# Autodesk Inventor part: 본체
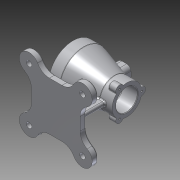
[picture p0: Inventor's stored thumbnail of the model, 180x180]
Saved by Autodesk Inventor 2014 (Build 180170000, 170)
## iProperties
Created: 2018-03
Part Number: 본체
Material: 알루미늄 6061
Document SubType Name: Modeling
Designer: kb542
Density: 2.71 g/cm^3
Appearance: 알루미늄 - 평지
Author: kb542
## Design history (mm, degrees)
sketch "스케치1"
  geometry: L1 (-50, 0)-(50, 0); L2 (-50, 0)-(-50, 45); L3 (-50, 45)-(-30, 45); L4 (50, 27.5)-(50, 0); L5 (-30, 45)-(27, 27.5); L6 (27, 27.5)-(50, 27.5); 2 further points
  constraints: 12 end point, 2 perpendicular, 1 coincident, 1 horizontal, 1 midpoint, 1 parallel
  dimensions: "d0" = 100 distance of L1.start L1.end; "d1" = 20 distance from line of L3.end L2; "d2" = 90 diameter of L3 L1; "d3" = 55 diameter of L6 L1; "d4" = 23 distance from line of L5.end L4
revolve "회전1" sketch "스케치1" stored, may be unused: angle "d5" = 90 deg
sketch "스케치2"
  geometry: L1 (-50, -45)-(-50, 45) reference; L2 (-30, -45)-(-30, 45) reference; L3 (27, -27.5)-(27, 27.5) reference; L4 (50, -27.5)-(50, 27.5) reference; L5 (-50, 0)-(50, 0) reference; L6 (-50, 0)-(-50, 35); L7 (-50, 35)-(-27, 35); L8 (-27, 35)-(-27, 26); L9 (-27, 26)-(20, 26); L10 (20, 26)-(20, 20); L11 (20, 20)-(50, 20); 3 further points
  constraints: 12 end point, 3 perpendicular, 2 parallel, 2 point on line
  dimensions: "d6" = 40 diameter of L11 L5; "d7" = 70 diameter of L7 L5; "d8" = 23 distance between parallel lines of L1 L8; "d9" = 30 distance from line of L11.end L10; "d10" = 47 distance between parallel lines of L10 L8 (derived); "d11" = 52 diameter of L9 L5
revolve "회전2" sketch "스케치2" stored, may be unused: angle "d12" = 90 deg
sketch "스케치3" dims "d13" = 55
  geometry: L1 (0, 0)-(0, 45.507); C1 r 27.5 at (0, 0) reference; C2 r 7 at (0, 27.5)
  constraints: 2 end point, 1 centre point, 1 coincident, 1 point on line, 1 vertical, 1 vertical alignment, 2 other
  dimensions: "d14" = 14 diameter of C2
extrude "돌출1" join sketch "스케치3" distance "d15" = 15; taper "d16" = 0 deg
hole "구멍1" diameter "d22" = 3.242; stored, may be unused: countersink angle "d26" = 90 deg, drill point angle "d28" = 118 deg; dims "d20" = 10, "d21" = 10, "d23" = 9, "d24" = 4, "d25" = 2, "d27" = 11
fillet "모깎기1" dims "d29" = 3
fillet "모깎기2" dims "d30" = 1
sketch "스케치4" dims "d31" = 80
  geometry: C1 r 35 at (0, 0) reference; C2 r 45 at (0, 0) reference; 2 further points
  constraints: 2 vertical alignment, 1 coincident, 2 other
hole "구멍2" sketch "스케치4" at (0, 40) diameter "d32" = 3.242; stored, may be unused: countersink angle "d36" = 90 deg, drill point angle "d38" = 118 deg; dims "d33" = 9, "d34" = 4, "d35" = 2, "d37" = 11
node "작업 평면1"
sketch "스케치5"
  geometry: L1 (-90, -7)-(-90, 7) reference; L2 (10, 45)-(10, -45) reference; L3 (-52.5, 12.5)-(-27.5, 12.5); L4 (-27.5, 12.5)-(-27.5, -12.5); L5 (-27.5, -12.5)-(-52.5, -12.5); L6 (-52.5, -12.5)-(-52.5, 12.5); L7 (-47.5, 7.5)-(-32.5, 7.5); L8 (-32.5, 7.5)-(-32.5, -7.5); L9 (-32.5, -7.5)-(-47.5, -7.5); L10 (-47.5, -7.5)-(-47.5, 7.5); 8 further points
  constraints: 16 end point, 5 midpoint, 4 parallel, 3 horizontal alignment, 2 horizontal, 2 perpendicular, 2 vertical alignment
  dimensions: "d42" = 25 distance of L3.start L3.end; "d43" = 25 distance between parallel lines of L3 L5; "d46" = 15 distance of L7.start L7.end; "d47" = 15 distance between parallel lines of L9 L7
extrude "돌출2" join sketch "스케치5" stored distance "d48" = 15; taper "d49" = 0 deg
extrude "돌출3" cut sketch "스케치5" stored distance "d50" = 15; taper "d51" = 0 deg
fillet "모깎기3" dims "d52" = 8
fillet "모깎기4" dims "d53" = 3
fillet "모깎기5" dims "d54" = 1
node "작업 평면2"
sketch "스케치6"
  geometry: L1 (-50, 27.5)-(-50, 7.718) reference; L2 (50, 45)-(50, -45) reference; L3 (50, 45)-(50, -45) reference; L4 (30, 45)-(30, -45) reference; L5 (50, -45)-(30, -45) reference; L6 (-50, -7.718)-(-50, -27.5) reference; L7 (-50, -7)-(-50, 7) reference; L8 (-45, 45)-(45, 45); L9 (45, 45)-(45, -45); L10 (45, -45)-(-45, -45); L11 (-45, -45)-(-45, 45); L12 (0, 0)-(-49.497, 49.497); L13 (0, 0)-(-70, 0); L14 (0, 0)-(0, 45); L15 (0, 0)-(45, -45); L16 (-45, -45)-(45, 45); L17 (45, 0)-(0, 0); A1 r 70 centre (0, 0) between (-70, 0) and (-49.497, 49.497); A2 r 18 centre (-49.497, 49.497) between (-58.08, 33.675) and (-33.675, 58.08); A3 r 25 centre (-70, 11.7) between (-45, 11.7) and (-58.08, 33.675); A4 r 25 centre (-70, -11.7) between (-58.08, -33.675) and (-45, -11.7); A5 r 18 centre (49.497, -49.497) between (58.08, -33.675) and (33.675, -58.08); A6 r 25 centre (70, 11.7) between (58.08, 33.675) and (45, 11.7); A7 r 25 centre (70, -11.7) between (45, -11.7) and (58.08, -33.675); A8 r 25 centre (-11.7, -70) between (-11.7, -45) and (-34.898, -60.681); A9 r 25 centre (11.7, -70) between (33.675, -58.08) and (11.7, -45); A10 r 25 centre (-11.7, 70) between (-33.675, 58.08) and (-11.7, 45); A11 r 25 centre (11.7, 70) between (11.7, 45) and (33.675, 58.08); 13 further points
  constraints: 25 point on circle, 21 end point, 19 symmetric about line, 11 centre point, 5 perpendicular, 4 point on line, 4 tangent, 3 midpoint, 2 coincident, 2 parallel, 1 horizontal, 1 horizontal alignment, 1 vertical alignment, 16 other
  dimensions: "d56" = 90 distance between parallel lines of L10 L8; "d57" = 90 distance between parallel lines of L11 L9; "d58" = 140 diameter of A1; "d59" = 45 deg angle of L13 L12; "d60" = 36 diameter of A2; "d63" = 25 radius of A4; "d64" = 25 radius of A3; "d67" = 25 radius of A8
extrude "돌출4" join sketch "스케치6" distance "d68" = 12; taper "d69" = 0 deg
fillet "모깎기6" dims "d70" = 25
fillet "모깎기7" dims "d71" = 25
sketch "스케치7"
  geometry: A1 r 18 centre (49.497, 49.497) between (58.08, 33.675) and (33.675, 58.08) reference; A2 r 18 centre (-49.497, 49.497) between (-33.675, 58.08) and (-58.08, 33.675) reference; A3 r 18 centre (-49.497, -49.497) between (-58.08, -33.675) and (-33.675, -58.08) reference; A4 r 18 centre (49.497, -49.497) between (33.675, -58.08) and (58.08, -33.675) reference; 5 further points
  constraints: 4 coincident
hole "구멍3" sketch "스케치7" at (-49.497, 49.497), (49.497, 49.497), (49.497, -49.497), (-49.497, -49.497) diameter "d73" = 10; stored, may be unused: countersink angle "d77" = 90 deg, drill point angle "d79" = 118 deg; dims "d74" = 9, "d75" = 4, "d76" = 2, "d78" = 11
chamfer "모따기1" distance "d80" = 3; stored, may be unused: second distance "d81" = 2, angle "d82" = 45 deg
chamfer "모따기2" distance "d83" = 1; stored, may be unused: second distance "d84" = 2, angle "d85" = 45 deg
fillet "모깎기8" dims "d86" = 3
chamfer "모따기3" distance "d87" = 1; stored, may be unused: second distance "d88" = 2, angle "d89" = 45 deg
node "작업 평면3"
sketch "스케치8"
  geometry: L1 (-70, -11.7)-(-70, 11.7) reference; L2 (-70, 11.7)-(-70, 36.312) reference; L3 (-70, -36.312)-(-70, -11.7) reference; L4 (-70, 64.497)-(-70, 36.312) reference; L5 (-70, -36.312)-(-70, -64.497) reference; L6 (-70, 24)-(-28.464, 20.366); L7 (-70, -24)-(-28.464, -20.366); L8 (-70, 24)-(-70, -24); A1 r 35 centre (0, 0) between (-28.464, 20.366) and (-28.464, -20.366) reference; A2 r 35 centre (0, 0) between (-28.464, 20.366) and (-28.464, -20.366); 3 further points
  constraints: 6 end point, 4 point on circle, 2 point on line, 1 centre point, 1 coincident, 1 collinear, 1 equal length
  dimensions: "d91" = 24 vertical distance of point (0, 0) L6.start; "d92" = 95 deg angle of L6 L2; "d93" = 95 deg angle of L5 L7
extrude "돌출5" join sketch "스케치8" stored distance "d94" = 8; taper "d95" = 0 deg
node "작업 평면4"
sketch "스케치9"
  geometry: L1 (-50, -45)-(-30, -45) reference; L2 (-30, -45)-(27, -27.5) reference; L3 (50, -6.513)-(38, -6.513) reference; L4 (50, 26.395)-(50, -6.513) reference; L5 (38, 26.395)-(50, 26.395) reference; L6 (34, 27.237)-(34, 27.237) reference; L7 (50, 26.395)-(38, 26.395) reference; L8 (50, -6.513)-(50, 26.395) reference; L9 (38, -6.513)-(50, -6.513) reference; L10 (34, -16.905)-(34, -10.332) reference; L11 (50, -19.881)-(38, -19.881) reference; L12 (50, -19.881)-(50, -19.881) reference; L13 (38, -19.881)-(50, -19.881) reference; L14 (34, -10.332)-(34, -16.905) reference; L15 (27, -27.5)-(27, 27.5) reference; L16 (4, -28.464)-(4, -70) reference; L17 (-4, -70)-(-4, -30.777) reference; L18 (-11.7, -70)-(-36.312, -70) reference; L19 (-64.497, -70)-(-36.312, -70) reference; L20 (36.312, -70)-(11.7, -70) reference; L21 (36.312, -70)-(64.497, -70) reference; L22 (11.7, -70)-(-11.7, -70) reference; L23 (27, -27.5)-(50, -27.5) reference; L24 (-37, -45)-(-37, -70); L25 (37, -70)-(37, -27.5); 3 further points
  constraints: 4 end point, 4 point on line, 1 perpendicular, 1 vertical, 6 other
  dimensions: "d97" = 37 distance from line of L24 point (0, 0); "d98" = 37 distance from line of point (0, 0) L25
feature "리브1" sketch "스케치9" dims "d99" = 1, "d100" = 8, "d101" = 0, "d102" = 0, "d103" = 1, "d104" = 1
fillet "모깎기9" dims "d105" = 3
fillet "모깎기10" dims "d106" = 3
fillet "모깎기11" dims "d107" = 3
sketch "스케치11"
  geometry: L1 (45, -11.7)-(45, 11.7) reference; 2 further points
  constraints: 1 other
  dimensions: "d108" = 45 distance from line of L1 point (0, -35); "d109" = 35 distance of point (0, -35) point (0, 0)
feature "엠보싱1" sketch "스케치11" dims "d0" = 100, "d1" = 20, "d2" = 90, "d3" = 55, "d4" = 23, "d110" = 0.5, "d111" = 0
node "솔리드1"
pattern_circular "원형 패턴1" dims "d18" = 360 deg
pattern_circular "원형 패턴2" dims angle "d40" = 360 deg
mirror "대칭1"
node "투영된 루프1"
node "투영된 루프2"
node "투영된 루프3"
node "투영된 루프4"
other parameters: "d55" = -82, "d90" = 0, "d96" = 0
